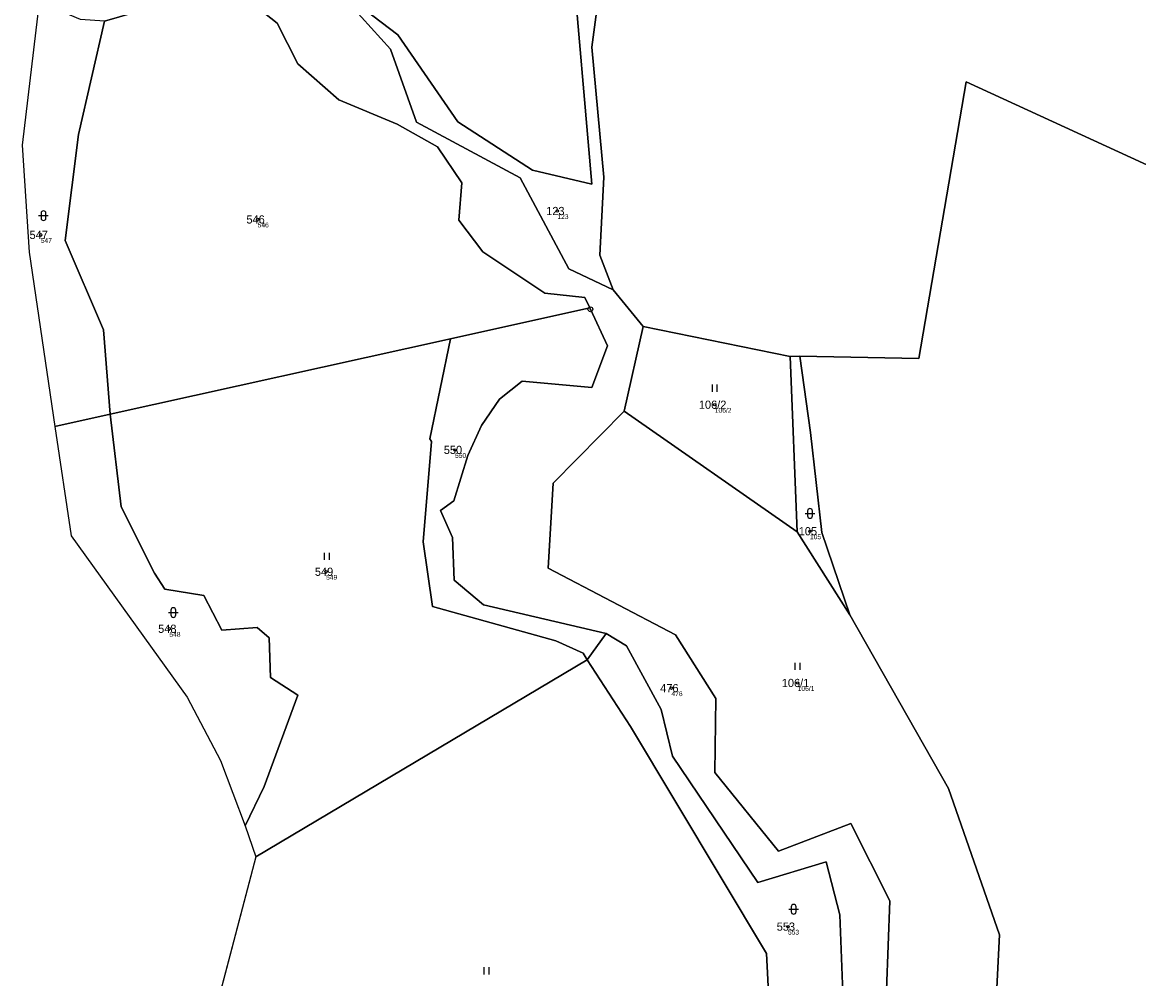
# Model space of a CAD drawing. Extents: x -700238 to -698499, y -1070626 to -1068006.
# Drawn here: x -700206.2 to -699975.1, y -1069108.8 to -1068910.8 of the extents above; entities that cross this region are included whole.
import ezdxf

# ---------------------------------------------------------------- set-up
doc = ezdxf.new("R2010")
doc.units = 0
for name, color, linetype in [('Definiční body', 7, 'Continuous'), ('Hranice parcel', 7, 'Continuous'), ('Parcelní čísla', 7, 'Continuous'), ('Polygon ku', 7, 'Continuous'), ('Polygon parcely', 7, 'Continuous'), ('Značky bodu BP', 7, 'Continuous'), ('Značky kultur', 7, 'Continuous')]:
    doc.layers.add(name, color=color, linetype=linetype)

msp = doc.modelspace()

# ---------------------------------------------------------------- linework, layer by layer
at = {"layer": 'Definiční body'}
for centre in [(-700095.46, -1068949.88994), (-700157.51, -1068951.62994), (-700202.4, -1068954.82994), (-700062.88, -1068989.98994), (-700116.65, -1068999.33994), (-700043.18, -1069016.17994), (-700143.34, -1069024.56994), (-700175.78, -1069036.36994), (-700071.86, -1069048.65994), (-700045.72, -1069047.58994), (-700047.74, -1069098.02994)]:
    msp.add_circle(centre, 0.25, dxfattribs=at)
at = {"layer": 'Hranice parcel'}
for p, q in [((-700202.74, -1068906.65), (-700206.22, -1068936.25)), ((-700206.22, -1068936.25), (-700204.79, -1068958.38)), ((-700204.79, -1068958.38), (-700199.47, -1068994.48)), ((-700077.69, -1068973.77), (-700083.9, -1068966.21)), ((-700088.76, -1068969.95), (-700117.62, -1068976.34)), ((-700081.63, -1068991.35), (-700077.69, -1068973.77)), ((-700047.3, -1068980.01), (-700077.69, -1068973.77)), ((-700117.62, -1068976.34), (-700188.04, -1068991.95)), ((-700045.28, -1068979.92), (-700047.3, -1068980.01)), ((-700047.3, -1068980.01), (-700045.81, -1069016.33)), ((-700045.81, -1069016.33), (-700081.63, -1068991.35)), ((-700188.04, -1068991.95), (-700199.47, -1068994.48)), ((-700199.47, -1068994.48), (-700196.14, -1069017.11)), ((-700045.81, -1069016.33), (-700034.9, -1069033.46)), ((-700196.14, -1069017.11), (-700172.11, -1069050.54)), ((-700085.37, -1069037.36), (-700089.28, -1069042.77)), ((-700157.89, -1069083.6), (-700089.28, -1069042.77)), ((-700160.12, -1069077.18), (-700157.89, -1069083.6)), ((-700157.89, -1069083.6), (-700171.46, -1069135.31))]:
    msp.add_line(p, q, dxfattribs=at)
for points in [[(-700083.9, -1068966.21), (-700086.67, -1068959.04), (-700085.85, -1068942.85), (-700088.31, -1068916), (-700084.83, -1068889.46), (-700041.76, -1068751.13), (-700013.43, -1068660.75)], [(-700142, -1068903.05), (-700128.49, -1068913.45), (-700116.07, -1068931.44), (-700100.59, -1068941.42), (-700088.35, -1068944.3), (-700092.52, -1068895.7), (-700089.53, -1068890.88)], [(-700142, -1068903.05), (-700129.99, -1068916.36), (-700124.62, -1068931.52), (-700103.17, -1068943.03), (-700093.07, -1068961.88), (-700083.9, -1068966.21)], [(-700189.2, -1068910.59), (-700166.97, -1068904.1), (-700160.05, -1068905.77), (-700153.49, -1068911.01), (-700149.2, -1068919.39), (-700140.71, -1068926.86), (-700128.65, -1068931.9), (-700120.26, -1068936.58), (-700115.25, -1068944.06), (-700115.85, -1068951.76), (-700110.9, -1068958.31), (-700098.09, -1068966.88), (-700089.77, -1068967.8), (-700088.76, -1068969.95)], [(-700188.04, -1068991.95), (-700189.41, -1068974.52), (-700197.34, -1068955.98), (-700194.57, -1068934.05), (-700189.2, -1068910.59)], [(-699886.24, -1068990.68), (-699927.83, -1068963.6), (-699966.54, -1068943.51), (-700010.84, -1068923.12), (-700020.68, -1068980.4), (-700045.28, -1068979.92)], [(-700088.76, -1068969.95), (-700088.63, -1068970.23), (-700085.06, -1068977.79), (-700088.36, -1068986.41), (-700102.74, -1068985.11), (-700107.44, -1068988.87), (-700111.2, -1068994.26), (-700113.97, -1069000.48), (-700116.89, -1069009.89), (-700119.63, -1069011.89), (-700117.19, -1069017.45), (-700116.82, -1069026.3), (-700110.79, -1069031.4), (-700085.37, -1069037.36)], [(-700089.28, -1069042.77), (-700090.15, -1069041.43), (-700095.82, -1069038.88), (-700121.35, -1069031.79), (-700123.27, -1069018.35), (-700121.5, -1068997.61), (-700121.86, -1068997.06), (-700117.62, -1068976.34)], [(-700034.9, -1069033.46), (-700040.74, -1069016.45), (-700043.09, -1068995.75), (-700045.28, -1068979.92)], [(-700027.33, -1069111.21), (-700026.63, -1069092.7), (-700034.7, -1069076.66), (-700049.69, -1069082.4), (-700062.86, -1069066.12), (-700062.68, -1069050.83), (-700070.99, -1069037.66), (-700097.4, -1069023.81), (-700096.33, -1069006.23), (-700081.63, -1068991.35)], [(-700188.04, -1068991.95), (-700185.79, -1069011.12), (-700178.86, -1069024.88), (-700176.71, -1069028.16), (-700168.67, -1069029.49), (-700164.92, -1069036.68), (-700157.63, -1069036.08), (-700155.11, -1069038.27), (-700154.86, -1069046.45), (-700149.17, -1069050.1), (-700156.19, -1069069.01), (-700160.12, -1069077.18)], [(-700034.9, -1069033.46), (-700014.52, -1069069.43), (-700003.97, -1069099.76), (-700004.92, -1069118.95)], [(-700085.37, -1069037.36), (-700081.17, -1069039.9), (-700073.99, -1069053.06), (-700071.62, -1069062.77), (-700054, -1069088.93), (-700039.82, -1069084.64), (-700036.97, -1069095.58), (-700035.98, -1069122.48), (-700040.87, -1069127.32), (-700051.79, -1069138.15), (-700055.65, -1069137.28), (-700057.91, -1069143.63), (-700058.06, -1069150.36), (-700057.59, -1069153.66)], [(-700089.28, -1069042.77), (-700080.34, -1069056.58), (-700052.16, -1069103.61), (-700051.73, -1069113.03), (-700054.71, -1069129.86), (-700061.3, -1069143.2), (-700068.97, -1069153.77)], [(-700172.11, -1069050.54), (-700165.2, -1069063.61), (-700160.12, -1069077.18)]]:
    msp.add_lwpolyline(points, dxfattribs=at)
at = {"layer": 'Polygon ku'}
msp.add_lwpolyline([(-700202.74, -1068906.65), (-700206.22, -1068936.25), (-700204.79, -1068958.38), (-700199.47, -1068994.48), (-700196.14, -1069017.11), (-700172.11, -1069050.54), (-700165.2, -1069063.61), (-700160.12, -1069077.18), (-700157.89, -1069083.6), (-700171.46, -1069135.31), (-700174.05, -1069154.77), (-700185.93, -1069246.25), (-700069.54, -1069293.44), (-700041.36, -1069305.51), (-700005.92, -1069321.74)], dxfattribs=at)
at = {"layer": 'Polygon parcely'}
for points in [[(-700084.83, -1068889.46), (-700041.76, -1068751.13), (-700013.43, -1068660.75), (-700041.57, -1068744.09), (-700063.74, -1068811.76), (-700082.46, -1068869.21), (-700087.92, -1068885.97), (-700089.53, -1068890.88), (-700092.52, -1068895.7), (-700088.35, -1068944.3), (-700100.59, -1068941.42), (-700116.07, -1068931.44), (-700128.49, -1068913.45), (-700142, -1068903.05), (-700129.99, -1068916.36), (-700124.62, -1068931.52), (-700103.17, -1068943.03), (-700093.07, -1068961.88), (-700083.9, -1068966.21), (-700086.67, -1068959.04), (-700085.85, -1068942.85), (-700088.31, -1068916)], [(-700088.35, -1068944.3), (-700092.52, -1068895.7), (-700089.53, -1068890.88), (-700158.24, -1068860.67), (-700180.4, -1068850.93), (-700185.15, -1068868.36), (-700182.79, -1068868.56), (-700183.42, -1068893.04), (-700178.18, -1068901.71), (-700162.71, -1068898.4), (-700155.48, -1068897.87), (-700142, -1068903.05), (-700128.49, -1068913.45), (-700116.07, -1068931.44), (-700100.59, -1068941.42)], [(-700189.2, -1068910.59), (-700194.57, -1068934.05), (-700197.34, -1068955.98), (-700189.41, -1068974.52), (-700188.04, -1068991.95), (-700117.62, -1068976.34), (-700088.76, -1068969.95), (-700089.77, -1068967.8), (-700098.09, -1068966.88), (-700110.9, -1068958.31), (-700115.85, -1068951.76), (-700115.25, -1068944.06), (-700120.26, -1068936.58), (-700128.65, -1068931.9), (-700140.71, -1068926.86), (-700149.2, -1068919.39), (-700153.49, -1068911.01), (-700160.05, -1068905.77), (-700166.97, -1068904.1)], [(-700204.79, -1068958.38), (-700199.47, -1068994.48), (-700188.04, -1068991.95), (-700189.41, -1068974.52), (-700197.34, -1068955.98), (-700194.57, -1068934.05), (-700189.2, -1068910.59), (-700194.21, -1068910.26), (-700202.74, -1068906.65), (-700206.22, -1068936.25)], [(-699927.83, -1068963.6), (-699966.54, -1068943.51), (-700010.84, -1068923.12), (-700020.68, -1068980.4), (-700045.28, -1068979.92), (-700043.09, -1068995.75), (-700040.74, -1069016.45), (-700034.9, -1069033.46), (-700014.52, -1069069.43), (-700003.97, -1069099.76), (-700004.92, -1069118.95), (-699942.21, -1069155.36), (-699887.09, -1069189.8), (-699876.74, -1069160.5), (-699858.28, -1069127.86), (-699826.38, -1069090.56), (-699861.15, -1069061.15), (-699908.65, -1069027.8), (-699886.24, -1068990.68)], [(-700088.76, -1068969.95), (-700117.62, -1068976.34), (-700121.86, -1068997.06), (-700121.5, -1068997.61), (-700123.27, -1069018.35), (-700121.35, -1069031.79), (-700095.82, -1069038.88), (-700090.15, -1069041.43), (-700089.28, -1069042.77), (-700085.37, -1069037.36), (-700110.79, -1069031.4), (-700116.82, -1069026.3), (-700117.19, -1069017.45), (-700119.63, -1069011.89), (-700116.89, -1069009.89), (-700113.97, -1069000.48), (-700111.2, -1068994.26), (-700107.44, -1068988.87), (-700102.74, -1068985.11), (-700088.36, -1068986.41), (-700085.06, -1068977.79), (-700088.63, -1068970.23)], [(-700047.3, -1068980.01), (-700077.69, -1068973.77), (-700081.63, -1068991.35), (-700045.81, -1069016.33)], [(-700157.89, -1069083.6), (-700089.28, -1069042.77), (-700090.15, -1069041.43), (-700095.82, -1069038.88), (-700121.35, -1069031.79), (-700123.27, -1069018.35), (-700121.5, -1068997.61), (-700121.86, -1068997.06), (-700117.62, -1068976.34), (-700188.04, -1068991.95), (-700185.79, -1069011.12), (-700178.86, -1069024.88), (-700176.71, -1069028.16), (-700168.67, -1069029.49), (-700164.92, -1069036.68), (-700157.63, -1069036.08), (-700155.11, -1069038.27), (-700154.86, -1069046.45), (-700149.17, -1069050.1), (-700156.19, -1069069.01), (-700160.12, -1069077.18)], [(-700047.3, -1068980.01), (-700045.81, -1069016.33), (-700034.9, -1069033.46), (-700040.74, -1069016.45), (-700043.09, -1068995.75), (-700045.28, -1068979.92)], [(-700081.63, -1068991.35), (-700096.33, -1069006.23), (-700097.4, -1069023.81), (-700070.99, -1069037.66), (-700062.68, -1069050.83), (-700062.86, -1069066.12), (-700049.69, -1069082.4), (-700034.7, -1069076.66), (-700026.63, -1069092.7), (-700027.33, -1069111.21), (-700005.74, -1069120.31), (-700004.92, -1069118.95), (-700003.97, -1069099.76), (-700014.52, -1069069.43), (-700034.9, -1069033.46), (-700045.81, -1069016.33)], [(-700160.12, -1069077.18), (-700156.19, -1069069.01), (-700149.17, -1069050.1), (-700154.86, -1069046.45), (-700155.11, -1069038.27), (-700157.63, -1069036.08), (-700164.92, -1069036.68), (-700168.67, -1069029.49), (-700176.71, -1069028.16), (-700178.86, -1069024.88), (-700185.79, -1069011.12), (-700188.04, -1068991.95), (-700199.47, -1068994.48), (-700196.14, -1069017.11), (-700172.11, -1069050.54), (-700165.2, -1069063.61)], [(-700061.3, -1069143.2), (-700068.97, -1069153.77), (-700057.59, -1069153.66), (-700058.06, -1069150.36), (-700057.91, -1069143.63), (-700055.65, -1069137.28), (-700051.79, -1069138.15), (-700040.87, -1069127.32), (-700035.98, -1069122.48), (-700036.97, -1069095.58), (-700039.82, -1069084.64), (-700054, -1069088.93), (-700071.62, -1069062.77), (-700073.99, -1069053.06), (-700081.17, -1069039.9), (-700085.37, -1069037.36), (-700089.28, -1069042.77), (-700080.34, -1069056.58), (-700052.16, -1069103.61), (-700051.73, -1069113.03), (-700054.71, -1069129.86)], [(-700174.05, -1069154.77), (-700068.97, -1069153.77), (-700061.3, -1069143.2), (-700054.71, -1069129.86), (-700051.73, -1069113.03), (-700052.16, -1069103.61), (-700080.34, -1069056.58), (-700089.28, -1069042.77), (-700157.89, -1069083.6), (-700171.46, -1069135.31)]]:
    msp.add_lwpolyline(points, close=True, dxfattribs=at)
for points in [[(-700084.83, -1068889.46), (-700088.31, -1068916), (-700085.85, -1068942.85), (-700086.67, -1068959.04), (-700083.9, -1068966.21), (-700077.69, -1068973.77), (-700047.3, -1068980.01), (-700045.28, -1068979.92), (-700020.68, -1068980.4), (-700010.84, -1068923.12), (-699966.54, -1068943.51), (-699927.83, -1068963.6), (-699886.24, -1068990.68), (-699875.07, -1068971.88), (-699827.95, -1069004.47), (-699797.12, -1069027.52), (-699794.77, -1069018.3), (-699797.43, -1069010.33), (-699866.1, -1068962.85), (-699970.6, -1068900.08)], [(-700077.69, -1068973.77), (-700083.9, -1068966.21), (-700093.07, -1068961.88), (-700103.17, -1068943.03), (-700124.62, -1068931.52), (-700129.99, -1068916.36), (-700142, -1068903.05)], [(-700160.05, -1068905.77), (-700153.49, -1068911.01), (-700149.2, -1068919.39), (-700140.71, -1068926.86), (-700128.65, -1068931.9), (-700120.26, -1068936.58), (-700115.25, -1068944.06), (-700115.85, -1068951.76), (-700110.9, -1068958.31), (-700098.09, -1068966.88), (-700089.77, -1068967.8), (-700088.76, -1068969.95), (-700088.63, -1068970.23), (-700085.06, -1068977.79), (-700088.36, -1068986.41), (-700102.74, -1068985.11), (-700107.44, -1068988.87), (-700111.2, -1068994.26), (-700113.97, -1069000.48), (-700116.89, -1069009.89), (-700119.63, -1069011.89), (-700117.19, -1069017.45), (-700116.82, -1069026.3), (-700110.79, -1069031.4), (-700085.37, -1069037.36), (-700081.17, -1069039.9), (-700073.99, -1069053.06), (-700071.62, -1069062.77), (-700054, -1069088.93), (-700039.82, -1069084.64), (-700036.97, -1069095.58), (-700035.98, -1069122.48)], [(-699969.55, -1069332.87), (-699976.24, -1069304.98), (-699991.98, -1069297.84), (-700003.25, -1069293.37), (-700017.96, -1069281.2), (-700015.45, -1069254.19), (-700031.95, -1069232.67), (-700047.83, -1069221.71), (-700037.56, -1069194.48), (-700054.16, -1069168.28), (-700027.33, -1069111.21), (-700026.63, -1069092.7), (-700034.7, -1069076.66), (-700049.69, -1069082.4), (-700062.86, -1069066.12), (-700062.68, -1069050.83), (-700070.99, -1069037.66), (-700097.4, -1069023.81), (-700096.33, -1069006.23), (-700081.63, -1068991.35), (-700077.69, -1068973.77)]]:
    msp.add_lwpolyline(points, dxfattribs=at)
at = {"layer": 'Značky bodu BP'}
for radius in [0.5, 0.0303]:
    msp.add_circle((-700088.63, -1068970.22988), radius, dxfattribs=at)
at = {"layer": 'Značky kultur'}
for p, q in [((-700202.841, -1068950.851), (-700200.839, -1068950.851)), ((-700202.341, -1068950.351), (-700202.341, -1068951.352)), ((-700201.339, -1068951.352), (-700201.339, -1068950.351)), ((-700063.391, -1068987.29), (-700063.391, -1068985.79)), ((-700062.39, -1068987.29), (-700062.39, -1068985.79)), ((-700043.681, -1069011.981), (-700043.681, -1069012.982)), ((-700042.679, -1069012.982), (-700042.679, -1069011.981)), ((-700044.181, -1069012.481), (-700042.179, -1069012.481)), ((-700143.661, -1069022.13), (-700143.661, -1069020.63)), ((-700142.66, -1069022.13), (-700142.66, -1069020.63)), ((-700175.961, -1069033.011), (-700173.959, -1069033.011)), ((-700175.461, -1069032.511), (-700175.461, -1069033.512)), ((-700174.459, -1069033.512), (-700174.459, -1069032.511)), ((-700046.231, -1069044.89), (-700046.231, -1069043.39)), ((-700045.23, -1069044.89), (-700045.23, -1069043.39)), ((-700047.551, -1069094.441), (-700045.549, -1069094.441)), ((-700047.051, -1069093.941), (-700047.051, -1069094.942)), ((-700046.049, -1069094.942), (-700046.049, -1069093.941)), ((-700110.601, -1069107.95), (-700110.601, -1069106.45)), ((-700109.6, -1069107.95), (-700109.6, -1069106.45))]:
    msp.add_line(p, q, dxfattribs=at)
for centre, start, end in [((-700201.84, -1068950.3509), 0, 180), ((-700201.84, -1068951.3509), 180, 359.9878861), ((-700043.18, -1069011.9809), 0, 180), ((-700043.18, -1069012.9809), 180, 359.9878861), ((-700174.96, -1069032.5109), 0, 180), ((-700174.96, -1069033.5109), 180, 359.9878861), ((-700046.55, -1069093.9409), 0, 180), ((-700046.55, -1069094.9409), 180, 359.9878861)]:
    msp.add_arc(centre, 0.5, start, end, dxfattribs=at)

# ---------------------------------------------------------------- texts
at = {"layer": 'Definiční body'}
for s, p in [('123', (-700095.46, -1068951.546)), ('546', (-700157.51, -1068953.286)), ('547', (-700202.4, -1068956.486)), ('106/2', (-700062.88, -1068991.646)), ('550', (-700116.65, -1069000.996)), ('105', (-700043.18, -1069017.836)), ('549', (-700143.34, -1069026.226)), ('548', (-700175.78, -1069038.026)), ('476', (-700071.86, -1069050.316)), ('106/1', (-700045.72, -1069049.246)), ('553', (-700047.74, -1069099.686))]:
    msp.add_text(s, height=0.999996, dxfattribs=at).set_placement(p)
at = {"layer": 'Parcelní čísla'}
for s, p in [('123', (-700097.785, -1068950.739)), ('546', (-700159.835, -1068952.479)), ('547', (-700204.725, -1068955.68)), ('106/2', (-700066.178, -1068990.84)), ('550', (-700118.975, -1069000.19)), ('105', (-700045.505, -1069017.029)), ('549', (-700145.665, -1069025.42)), ('548', (-700178.105, -1069037.22)), ('106/1', (-700049.018, -1069048.44)), ('476', (-700074.185, -1069049.509)), ('553', (-700050.065, -1069098.88))]:
    msp.add_text(s, height=1.699998, dxfattribs=at).set_placement(p)

doc.saveas('drawing.dxf')
